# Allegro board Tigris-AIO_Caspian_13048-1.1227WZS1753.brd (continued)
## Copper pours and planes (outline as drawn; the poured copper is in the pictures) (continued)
VCC3 on L3: 1.65,18.14 1.65,247.76 3.3,249.41 101.6,249.41 101.85,249.16 101.85,245.86 101.22,245.22 98.93,245.22 98.68,245.47 92.71,245.47 92.71,243.87 93.22,243.37 93.22,242.86 93.01,242.66 89.18,242.66 84.84,247 51.44,247 50.67,246.24 49.66,246.24 49.15,246.74 30.73,246.74 30.48,246.49 8.13,246.49 5.08,243.44 5.08,190.74 9.46,186.36 9.46,182.04 10.54,180.96 10.54,170.29 14.61,166.23 14.61,137.14 5.71,128.25 5.71,113.52 6.6,112.63 6.6,107.04 5.59,106.03 5.59,94.34 6.86,93.07 6.86,90.28 4.83,88.25 4.83,85.84 6.22,84.44 6.22,61.45 5.71,60.94 5.71,49.77 10.29,45.2 10.29,43.67 9.02,42.4 9.02,41.77 10.54,40.24 10.54,36.43 12.45,34.53 12.45,26.78 22.61,16.62 22.61,14.46 29.84,7.22 35.43,7.22 36.2,6.46 69.98,6.46 71.25,5.19 71.25,2.4 70.61,1.76 18.03,1.76
VCC3 on L4: 110.08,245.22 112.39,242.91 112.39,229.85 112.14,229.6 112.14,226.68 118.11,220.71 119.25,220.71 119.32,220.77 119.38,220.71 123.32,220.71 123.32,220.76 126.59,220.76 126.62,220.74 153.77,220.74 154.56,219.95 154.56,219.44 154.05,218.93 142.24,218.93 141.86,218.55 141.86,217.15 142.24,216.77 143.26,216.77 143.64,217.15 154.76,217.15 159.16,221.55 169.39,221.55 169.82,221.12 170.41,221.12 170.84,221.55 170.84,224.95 169.95,225.84 119.23,225.84 118.96,226.11 118.83,226.11 118.16,226.78 118.16,248.12 117.04,249.23 103.56,249.23 103.5,249.28 99.95,249.28 99.19,248.52 99.19,245.73 99.69,245.22
VCC3 on L4: 144.02,100.19 144.15,100.31 145.29,100.31 145.92,100.95 145.92,106.28 148.59,108.95 149.73,108.95 149.86,108.82 149.86,108.44 147.19,105.77 147.19,100.19 146.05,99.04 144.15,99.04 144.02,99.17
VCC3 on L4: 114.76,57.24 114.43,56.91 114.43,55.1 114.68,54.85 118.87,54.85 122.91,50.81 122.91,45.63 121.95,44.66 121.95,43.52 122.43,43.04 124.61,43.04 124.97,43.39 124.97,51.8 119.53,57.24
VCC3_CAM on BOTTOM: 173.53,221.95 173.23,222.26 173.23,224.27 172.97,224.52 170.05,224.52 169.93,224.39 169.93,222.87 169.8,222.74 167.77,222.74 167.64,222.87 167.64,226.35 169.37,228.08 174.32,228.08 174.6,227.8 174.6,222.23 174.32,221.95 ; 4 cut-outs
VCC3_HDD on TOP: 8.38,89.9 7.87,90.41 7.87,92.57 6.35,94.09 5.46,94.09 5.08,94.47 5.08,96.12 5.46,96.5 7.11,96.5 10.16,93.46 10.16,90.66 9.4,89.9
VCC5_PANEL on TOP: 122.4,217.31 122.17,217.53 122.17,221.98 122.56,222.36 126.36,222.36 126.49,222.23 126.49,219.95 126.62,219.82 126.62,217.66 126.49,217.53 125.86,217.53 125.86,217.56 125.6,217.81 123.55,217.81 123.04,217.31 ; 9 cut-outs
VCC5_PANEL on BOTTOM: 121.54,216.9 121.28,217.15 121.28,223.5 121.41,223.63 124.97,223.63 126.24,222.36 126.24,220.2 122.94,216.9
VCC5_USB on TOP: 106.43,26.02 105.99,26.45 105.99,32.7 106.76,33.46 109.98,33.46 109.98,33.51 110.11,33.51 110.36,33.77 110.36,34.96 110.21,35.11 109.4,35.11 109.09,35.42 109.09,36.13 109.45,36.48 111.12,36.48 111.38,36.23 111.38,34.65 111.63,34.4 112.9,34.4 113.67,33.64 115.32,33.64 115.44,33.51 115.44,32.75 114.91,32.22 114.94,32.19 114.94,27.29 113.67,26.02 ; 9 cut-outs
VCC5_USB on BOTTOM: 181.99,106.28 180.85,107.43 180.85,110.73 181.25,111.13 186.39,111.13 186.74,110.78 186.74,109.05 185.62,107.93 185.62,106.87 185.04,106.28 ; 2 cut-outs
VCC5_USB on BOTTOM: 140.34,31.05 138.89,32.5 136.14,32.5 133.35,35.29 120.14,35.29 119.51,35.92 114.17,35.92 113.67,35.42 113.67,33.38 113.03,32.75 110.87,32.75 110.24,33.38 110.24,35.42 113.28,38.46 121.03,38.46 121.67,37.83 134.49,37.83 136.78,35.54 148.59,35.54 150.88,37.83 150.88,42.02 160.78,51.93 164.72,51.93 165.48,51.16 165.48,49.77 158.18,42.47 158.18,39.49 156.21,37.53 156.21,36.59 155.98,36.59 155.7,36.31 155.7,35.32 153.03,32.65 153.03,32.62 152.27,31.86 150.22,31.86 149.4,31.05
VCC5_USB on BOTTOM: 15.62,22.59 14.73,23.48 14.73,27.92 15.11,28.3 16.26,28.3 16.38,28.18 16.38,24.24 17.4,23.22 17.4,22.84 17.14,22.59 ; 2 cut-outs
VCC5_USB on L4: 167.07,47.93 172.85,53.7 172.85,55.23 174.05,56.44 174.05,58.34 174.88,59.17 174.88,66.4 175.39,66.91 175.39,69.83 175.01,70.21 175.01,78.22 173.99,79.23 173.99,81.39 173.23,82.15 172.34,82.15 169.04,85.45 169.04,92.31 170.43,93.71 178.18,93.71 178.56,94.09 181.61,94.09 183.51,96 183.51,107.68 183.01,108.19 180.09,108.19 180.09,98.92 178.44,97.27 168.91,97.27 165.86,94.22 165.86,82.91 168.66,80.12 168.66,77.83 168.72,77.77 168.72,74.6 168.78,74.53 168.78,73.26 170.18,71.87 170.18,70.21 170.31,70.09 170.31,66.15 168.53,64.37 168.53,59.12 166.62,57.21 166.62,55.99 166.67,55.94 166.67,55.43 163.19,51.95 163.19,49.39 164.66,47.93
VCC12 on TOP: 21.36,72.5 20.83,73.03 20.83,76.31 21.21,76.69 25.18,76.69 25.4,76.48 25.4,75.22 25.43,75.19 25.43,74 25.78,73.64 26.24,73.64 26.24,72.68 26.06,72.5 ; 1 cut-out
VCC12 on BOTTOM: 18.67,182.36 18.29,182.74 18.29,185.28 18.41,185.4 19.3,185.4 19.56,185.15 19.56,182.74 19.18,182.36 ; 1 cut-out
VCC12 on BOTTOM: 12.19,117.2 11.94,117.46 11.94,118.47 12.19,118.73 14.1,118.73 14.35,118.47 14.35,117.59 13.97,117.2 ; 1 cut-out
VCC12_FAN on BOTTOM: 7.75,184.51 6.86,185.4 6.86,190.23 7.62,190.99 14,190.99 14.4,190.59 14.4,189.98 13.46,189.04 13.46,184.64 13.34,184.51 ; 4 cut-outs
VCC12_HDD on TOP: 4.88,103.62 4.65,103.84 4.65,106.31 4.8,106.46 11.53,106.46 11.73,106.26 12.83,106.26 13.31,105.77 17.04,105.77 17.22,105.6 17.22,104 16.84,103.62 ; 2 cut-outs
VCC12_HDD_C on TOP: 17.6,105.65 17.17,106.08 13.46,106.08 13.16,106.38 13.16,107.65 13.31,107.81 18.34,107.81 18.92,107.22 18.92,105.9 18.67,105.65
VCC12_HDD_C on BOTTOM: 18.24,104.84 18.01,105.06 18.01,107.3 18.03,107.32 18.03,111.49 17.4,112.12 13.34,112.12 12.36,113.1 12.36,115.01 13.11,115.76 13.16,115.76 13.46,116.06 13.46,116.82 13.59,116.95 15.49,116.95 16,117.46 17.53,117.46 18.03,116.95 18.41,116.95 20.29,115.07 20.29,105.27 19.86,104.84 ; 2 cut-outs
VCC12CPU on TOP: 13.41,158.66 8.13,163.94 6.6,163.94 1.65,168.89 1.65,188.58 1.83,188.76 1.83,230.87 5.84,234.88 12.45,234.88 14.66,232.67 14.66,224.85 16.13,223.38 19.18,223.38 21.74,220.81 24.99,220.81 25.55,220.25 25.96,220.25 26.16,220.05 26.16,208.8 26.01,208.64 18.62,208.64 18.31,208.34 18.31,201.84 22.17,197.98 24.64,197.98 26.04,196.58 26.04,172.58 24.89,171.43 20.83,171.43 20.19,170.8 20.19,169.91 19.94,169.66 19.05,169.66 17.53,168.13 17.53,165.46 18.03,164.96 18.03,159.65 17.04,158.66
VCC12CPU on BOTTOM: 13,158.58 8.64,162.95 8.64,164.7 8.13,165.21 2.97,165.21 1.83,166.35 1.83,222.92 2.79,223.88 5.46,223.88 6.48,222.87 6.48,181.09 7.37,180.2 9.65,180.2 10.03,180.58 10.92,180.58 11.94,181.59 13.34,181.59 13.46,181.47 13.46,180.83 13.97,180.32 14.73,180.32 17.4,177.66 17.4,174.1 20.07,174.1 20.45,173.72 20.45,164.3 19.32,163.17 19.32,159 18.9,158.58
VIN12V_SYS on TOP: 69.52,29.14 68.91,29.75 67.21,29.75 66.93,30.03 66.93,32.78 70.1,35.95 70.1,46.21 71.02,47.13 76.58,47.13 77.41,46.3 77.41,40.46 78.36,39.51 78.36,37.07 74.14,32.85 74.14,29.85 73.43,29.14 ; 4 cut-outs
VIN12V_SYS on BOTTOM: 72.87,35.57 72.64,35.8 72.64,42.53 73.08,42.96 76.38,42.96 78.23,41.11 78.23,36.03 77.77,35.57
0D95V_VGA on TOP: 108.33,103.74 107.95,104.12 107.95,108.82 109.09,109.97 113.54,109.97 114.05,110.47 121.92,110.47 122.81,109.58 122.81,106.79 122.38,106.36 119.71,106.36 118.8,105.44 118.8,104.58 118.9,104.48 118.9,104.02 118.77,103.9 118.11,103.9 117.96,103.74 ; 2 cut-outs
0D95V_VGA_S0 on TOP: 104.65,95.36 104.39,95.61 104.39,99.55 107.51,102.66 108.01,102.66 108.33,102.98 114.6,102.98 114.88,102.7 114.88,100.26 109.98,95.36
0D95V_VGA_S0 on TOP: 80.4,91.14 79.92,91.62 79.59,91.62 79.13,91.17 78.4,91.17 77.91,91.66 76.79,91.66 75.52,92.93 75.52,94.61 75.79,94.88 75.79,95.64 75.92,95.76 76.5,95.76 76.83,95.43 76.83,94.63 77.01,94.45 79.59,94.45 79.84,94.71 80.35,94.71 82,93.05 82,92.42 80.72,91.14
0D95V_VGA_S0 on BOTTOM: 78.74,91.04 78.61,91.17 78.61,91.68 78.49,91.8 77.72,91.8 77.34,92.19 77.34,94.34 77.22,94.47 76.45,94.47 76.07,94.85 76.07,95.23 76.71,95.87 77.6,95.87 77.72,95.74 77.72,95.11 77.85,94.98 78.23,94.98 78.36,94.85 78.36,93.46 78.74,93.07 81.71,93.07 81.84,93.2 83.82,93.2 84.2,93.58 84.96,93.58 85.03,93.52 85.41,93.52 87.5,95.61 89.15,95.61 89.6,96.06 89.6,96.44 89.66,96.5 89.66,97.98 92.08,100.39 103.91,100.39 106.05,98.26 106.05,95.87 105.66,95.49 94.49,95.49 94.23,95.23 92.2,95.23 91.44,94.47 91.44,93.96 91.06,93.58 89.41,93.58 88.29,92.47 87.4,92.47 86.11,91.17 81.53,91.17 81.41,91.3 79.63,91.3 79.38,91.04 ; 12 cut-outs
1D05V_PWR on TOP: 150.55,105.72 150.39,105.88 150.39,107.86 153.44,110.91 154.05,110.91 154.64,111.49 158.75,111.49 159.51,112.25 160.66,112.25 160.68,112.28 164.82,112.28 164.97,112.12 164.97,106.66 164.72,106.41 161.04,106.41 160.4,105.77 160.02,105.77 159.98,105.74 158.28,105.74 158.27,105.72 ; 2 cut-outs
1D05V_SW on TOP: 168.45,103.64 165.86,106.23 165.86,112.61 168.25,115 172.36,115 172.39,115.02 172.54,114.87 172.54,110.04 172.24,109.74 172.24,107.63 172.54,107.32 172.54,103.9 172.29,103.64
1D05V_SW on L3: 171.7,113.65 167.26,113.65 165.86,112.25 165.86,106.66 166.75,105.77 171.45,105.77 172.21,106.54 172.21,113.14
1D5V_VGA_S0 on TOP: 48.03,84.2 47.9,84.33 45.77,84.33 45.69,84.4 45.69,84.91 45.79,85.01 47.5,85.01 47.62,85.14 47.62,86.03 47.44,86.22 45.97,86.22 45.85,86.34 45.85,96 45.94,96.09 47.37,96.09 47.52,95.94 47.52,93.74 48.09,93.16 48.09,91.35 47.93,91.18 47.92,91.18 47.51,90.78 47.51,89.78 47.12,89.39 47.12,87.61 47.38,87.35 47.95,87.35 48.13,87.53 48.13,88.87 48.26,89 49.02,89 49.86,88.16 49.86,84.61 49.45,84.2 ; 8 cut-outs
1D5V_VGA_S0 on TOP: 46.05,102.11 45.74,102.41 45.74,106.96 45.87,107.09 49.93,107.09 50.59,106.43 50.59,103.3 49.91,102.62 48.03,102.62 47.52,102.11 ; 8 cut-outs
1D5V_VGA_S0 on TOP: 45.72,74.22 45.54,74.4 45.54,75.56 45.74,75.77 45.74,78.79 45.84,78.89 46.48,78.89 46.91,79.32 48.26,79.32 48.79,78.79 48.79,77.95 50.24,76.5 50.24,75.46 49.73,74.95 49.02,74.95 48.28,74.22 ; 5 cut-outs
1D5V_VGA_S0 on TOP: 58.42,59.93 57.66,60.69 57.66,65.77 58.8,66.91 66.8,66.91 67.31,66.4 67.31,61.96 66.67,61.32 63.88,61.32 62.48,59.93
1D5V_VGA_S0 on BOTTOM: 46.58,72.41 45.74,73.25 45.74,78.76 45.92,78.94 47.37,78.94 47.52,79.09 49.32,79.09 49.81,78.61 49.81,77.49 49.32,77.01 48.79,77.01 48.61,76.83 48.61,76.15 49.02,75.74 49.63,75.74 50.01,76.12 50.44,76.12 50.59,75.97 50.59,74.32 50.44,74.17 50.24,74.17 49.73,74.68 49.07,74.68 48.79,74.4 48.79,73.79 49.02,73.56 49.27,73.56 49.45,73.74 49.81,73.74 49.88,73.66 49.88,72.54 49.76,72.41 ; 7 cut-outs
1D5V_VGA_S0 on BOTTOM: 45.85,99.93 45.72,100.06 45.72,106.28 45.99,106.55 47.57,106.55 47.7,106.43 47.7,100.64 47.62,100.57 46.99,100.57 46.35,99.93 ; 9 cut-outs
1D5V_VGA_S0 on BOTTOM: 57.66,77.2 57.66,79.23 58.93,80.5 58.93,84.82 59.05,84.95 59.44,84.95 59.69,85.2 59.69,87.23 58.67,88.25 58.67,91.42 55.88,94.22 55.88,96.12 56.01,96.25 56.39,96.25 58.55,94.09 58.55,93.96 60.07,92.44 60.71,92.44 61.34,91.8 61.34,91.04 62.23,90.15 63.63,90.15 64.64,89.14 69.09,89.14 69.34,89.39 69.34,91.7 69.75,92.11 73.2,92.11 73.66,92.57 73.66,93.84 73.79,93.96 75.06,93.96 75.31,94.22 76.07,94.22 76.2,94.09 76.2,91.93 75.82,91.55 75.82,85.33 75.95,85.2 75.95,81.64 75.56,81.26 74.93,81.26 74.17,80.5 70.1,80.5 68.71,81.9 62.1,81.9 58.67,78.47 58.67,77.71 58.17,77.2 ; 16 cut-outs
1D5V_VGA_S0 on BOTTOM: 49.15,82.9 47.72,84.33 45.92,84.33 45.74,84.51 45.74,87.17 45.92,87.35 47.65,87.35 47.83,87.53 47.83,88.06 46,89.89 46,93.8 46.2,94 47.95,94 48.33,93.62 48.33,89.59 49.76,88.16 49.76,83.11 49.55,82.9 ; 2 cut-outs
1D5V_VGA_S0 on L3: 49.4,79.22 47.24,79.22 46.99,78.97 46.99,74.14 49.4,71.73 54.85,71.73 55.5,72.37 55.5,73.63 54.86,74.27 54.23,74.27 52.7,72.74 50.54,72.74 50.04,73.25 50.04,75.67 49.53,76.17 49.53,79.09
1D5V_VGA_S0 on L4: 61.09,64.24 60.7,64.63 60.45,64.63 60.45,64.62 50.3,64.62 48.51,66.4 48.51,67.8 44.75,71.56 44.75,104.16 51.38,110.79 60.9,110.79 68.96,102.73 71.5,102.73 73.28,100.95 73.28,100.31 76.58,97.01 76.58,94.34 75.82,93.58 75.82,90.66 76.83,89.65 76.83,86.72 78.11,85.45 78.11,85.07 80.01,83.17 81.66,83.17 83.31,81.52 83.31,72.25 82.8,71.74 82.68,71.74 82.42,71.48 82.42,71.43 79.89,68.89 71.18,68.89 66.52,64.24 ; 1 cut-out
1D8V_VGA on TOP: 96.82,61.45 96.06,62.21 96.06,66.86 96.29,67.09 99.29,67.09 99.52,67.32 100.84,67.32 100.86,67.29 100.86,65.64 101.88,64.63 103.89,64.63 104.09,64.42 104.09,61.76 103.78,61.45 ; 2 cut-outs
1D8V_VGA_S0 on TOP: 90.82,97.71 90.71,97.82 90.71,98.23 90.77,98.28 91.19,98.28 92.91,100.01 92.91,100.02 93.19,100.3 93.21,100.3 94.11,101.2 94.11,103.87 94.74,104.5 95,104.5 95.12,104.38 95.12,100.06 95,99.93 94.23,99.93 93.98,99.68 93.88,99.68 91.91,97.71 ; 3 cut-outs
1P5_PCH_PWR on TOP: 124.71,48.75 123.95,49.51 123.95,55.1 124.33,55.48 126.75,55.48 127.89,54.34 127.89,52.18 129.03,51.04 131.19,51.04 131.32,50.91 131.32,48.88 131.19,48.75 ; 6 cut-outs
1P5_PCH_PWR on BOTTOM: 124.33,48.37 124.08,48.62 124.08,53.58 124.33,53.83 128.65,53.83 129.03,53.45 129.03,48.75 128.65,48.37
1P5_PCH_VCC3 on TOP: 131.95,44.05 131.7,44.31 131.7,52.69 131.95,52.94 134.24,52.94 134.62,52.56 134.62,49.77 134.75,49.64 136.4,49.64 136.53,49.51 136.53,47.23 133.35,44.05
3D3V_PWR on TOP: 98.7,45.75 98.48,45.98 90.93,45.98 90.37,46.54 90.37,51.09 92.15,52.87 95.28,52.87 96.88,51.27 98.96,51.27 99.39,50.83 99.39,46.26 98.88,45.75
3D3V_PWR on BOTTOM: 97.84,44.97 97.83,44.97 97.81,44.97 97.71,45.07 97.71,45.12 91.77,45.12 91.19,45.7 91.19,52.87 91.67,53.35 98.22,53.35 98.53,53.04 98.53,45.88 98.63,45.78 98.63,45.09 98.5,44.97 ; 1 cut-out
3D3V_VGA_S0 on TOP: 84.68,69.72 83.84,70.56 83.57,70.56 83.57,71.74 83.82,71.99 87.63,71.99 87.88,71.74 87.88,70.21 87.87,70.21 87.63,69.98 85.57,69.98 85.32,69.72 ; 1 cut-out
3D3V_VGA_S0 on BOTTOM: 50.77,133.21 49.91,134.07 49.91,142.78 46.23,146.47 46.23,148.8 46.61,149.18 50.44,149.18 53.72,145.91 53.72,133.77 53.16,133.21 ; 7 cut-outs
3D3V_VGA_S0 on L4: 51.16,131.71 54.08,131.71 54.69,132.32 54.69,140.19 52.3,142.58 51.05,142.58 50.74,142.26 50.71,142.26 50.55,142.1 50.55,131.94 50.8,131.68 51.13,131.68
1589_LX on TOP: 32.38,80.91 32.38,82.51 31.62,83.27 29.16,83.27 28.91,83.52 28.91,95.51 29.26,95.87 35.05,95.87 35.69,95.23 35.69,90.41 34.67,89.39 32.64,89.39 31.85,88.6 31.85,85.38 33.05,84.18 33.05,80.91
62883AGND on BOTTOM: 35.69,130.79 35.36,131.12 35.36,133.16 38.51,136.31 38.79,136.31 39.14,136.66 39.14,141.49 39.37,141.72 39.37,146.01 39.88,146.52 43.21,146.52 43.92,145.81 43.92,133.28 42.32,131.68 37.59,131.68 36.7,130.79 ; 6 cut-outs
CAP_1 on TOP: 59.69,35.8 59.56,35.92 59.56,36.94 59.82,37.19 60.33,37.19 60.58,36.94 60.58,36.05 60.33,35.8
CR_1P2V_LDOIN on BOTTOM: 178.69,153.53 178.56,153.65 178.56,154.16 178.94,154.54 179.32,154.54 179.71,154.92 179.71,155.18 180.09,155.56 180.59,155.56 180.59,154.8 179.32,153.53
CR_1P2V_LDOOUT on BOTTOM: 178.69,158.86 177.67,159.88 177.67,163.43 177.8,163.56 178.94,163.56 179.07,163.43 179.07,162.67 178.94,162.54 178.94,160.38 179.07,160.26 179.83,160.26 180.21,159.88 180.21,158.99 180.09,158.86 ; 5 cut-outs
CR_3P3V_PECI on BOTTOM: 178.69,154.67 178.56,154.8 178.56,155.43 178.94,155.81 179.83,155.81 179.83,155.56 179.45,155.18 179.45,154.92 179.2,154.67
DCBATOUT_1589 on TOP: 35.28,79.69 34.92,80.04 34.92,82.94 32.38,85.48 32.38,88.27 33.07,88.96 36.73,88.96 36.83,88.86 36.83,87.89 37.41,87.31 37.41,79.69 ; 1 cut-out
DCIN_+12V on TOP: 9.96,132.62 8.36,134.22 8.36,139.33 9.12,140.09 13.59,140.09 15.39,138.29 18.97,138.29 19.2,138.06 19.2,136.15 19.05,136 14.86,136 11.48,132.62
DCIN_+12V on BOTTOM: 17.96,129.98 17.81,130.13 17.81,130.67 17.27,131.2 9.55,131.2 7.87,132.88 7.87,139.18 7.24,139.81 7.24,142.48 8.64,143.87 13.08,143.87 14.1,142.86 17.48,142.86 17.7,143.09 17.7,145.93 17.55,146.08 17.55,146.87 17.73,147.05 19.25,147.05 19.46,146.85 19.46,146.31 19.05,145.91 19.05,144.99 18.77,144.71 18.77,130.21 18.54,129.98 ; 14 cut-outs
DDR_SW on TOP: 174.02,198.56 168.1,204.48 168.1,214.79 168.35,215.05 171.63,215.05 171.81,214.87 171.81,213.19 172.16,212.84 179.15,212.84 179.55,212.43 179.55,207.12 179.22,206.79 177.83,206.79 177.44,206.41 177.44,204.73 177.83,204.35 179.22,204.35 179.55,204.02 179.55,198.87 179.25,198.56
DDR_SW on BOTTOM: 173.86,198.74 168.15,204.45 168.15,211.95 169.04,212.84 178.69,212.84 179.58,211.95 179.58,199.25 179.07,198.74
DDR_VREF_PWR on BOTTOM: 133.48,108.19 132.84,108.82 132.84,110.85 132.97,110.98 137.29,110.98 138.18,111.87 138.18,114.41 139.06,115.3 145.54,115.3 146.05,114.79 146.05,109.08 145.16,108.19 ; 1 cut-out
DPLVDS_PIN12 on TOP: 127.81,206.92 127.64,207.1 127.64,208.52 128.02,208.9 128.52,208.9 128.65,208.77 128.65,208.14 128.78,208.01 129.03,208.01 129.18,207.86 129.18,207.02 129.08,206.92
DPLVDS_PIN12 on BOTTOM: 128.78,207.12 128.52,207.37 128.52,207.76 128.78,208.01 129.54,208.01 129.67,207.88 129.67,207.25 129.54,207.12
HDD_LED_5V on TOP: 2.92,40.12 2.67,40.37 2.67,45.96 3.81,47.1 6.48,47.1 6.73,46.85 6.73,44.56 8.89,42.4 8.89,40.37 8.64,40.12
LAN_1P05_OUT on TOP: 26.54,37.96 26.04,38.46 26.04,39.25 25.91,39.38 25.91,43.54 26.16,43.8 29.46,43.8 29.72,43.54 29.72,42.78 29.84,42.66 30.86,42.66 30.99,42.53 30.99,41.77 30.86,41.64 28.83,41.64 27.15,39.96 27.15,39.38 27.43,39.1 27.43,37.96 ; 2 cut-outs
MPV18 on BOTTOM: 75.9,75.24 75.77,75.37 75.77,80.17 75.56,80.37 75.16,80.37 75.06,80.48 75.06,81.04 75.16,81.14 75.69,81.14 76.12,80.71 76.12,80.22 76.33,80.02 76.33,78.98 76.45,78.85 76.45,75.35 76.35,75.24
Net_1 on BOTTOM: 4.95,130.29 9.02,130.29 9.14,130.16 9.14,128 8.79,127.64 4.8,127.64 4.57,127.87 4.57,129.9
PWM1_LX on TOP: 26.92,208.77 26.67,209.03 26.67,212.33 26.8,212.45 28.57,212.45 28.7,212.58 28.7,214.99 28.57,215.12 26.8,215.12 26.67,215.25 26.67,218.68 26.8,218.8 28.7,218.8 28.83,218.93 28.83,221.09 28.32,221.6 26.06,221.6 25.68,221.98 25.68,226.3 26.06,226.68 31.27,226.68 31.52,226.42 31.52,224.65 31.78,224.39 34.06,224.39 34.32,224.65 34.32,226.3 34.7,226.68 39.58,226.68 39.96,226.3 39.96,219.55 39.55,219.14 37.92,219.14 37.39,218.6 37.39,217.74 34.16,214.51 34.16,209.03 33.91,208.77
PWM1_LX on BOTTOM: 29.21,208.77 28.83,209.15 28.83,221.09 28.32,221.6 26.04,221.6 25.68,221.95 25.68,226.3 26.06,226.68 31.27,226.68 31.52,226.42 31.52,224.65 31.78,224.39 34.06,224.39 34.32,224.65 34.32,226.3 34.7,226.68 39.58,226.68 39.96,226.3 39.96,219.55 39.55,219.14 35,219.14 34.67,218.8 34.67,216.9 35.23,216.34 35.23,215.58 34.16,214.51 34.16,209.03 33.91,208.77
PWM1_LX on L3: 29.41,222.67 39.67,222.67 39.95,222.39 39.95,219.54 39.55,219.14 37.92,219.14 37.39,218.6 37.39,217.74 34.16,214.51 34.16,209.03 33.91,208.77 29.21,208.77 28.83,209.15 28.83,222.08
PWM2_LX on TOP: 26.67,185.78 26.54,185.91 26.54,189.09 26.67,189.21 28.19,189.21 28.57,189.59 28.57,191.88 28.32,192.13 26.67,192.13 26.54,192.26 26.54,195.31 26.67,195.44 28.64,195.44 28.77,195.56 28.77,197.66 28.77,197.66 28.77,198.29 28.45,198.61 26.44,198.61 26.06,198.99 26.06,203.31 26.44,203.69 31.65,203.69 31.9,203.44 31.9,201.66 32.16,201.41 34.44,201.41 34.7,201.66 34.7,203.31 35.08,203.69 39.96,203.69 40.34,203.31 40.34,195.9 40.11,195.67 37.21,195.67 36.83,195.28 36.83,193.89 34.29,191.35 34.29,186.17 33.91,185.78
PWM2_LX on BOTTOM: 29.01,185.78 28.75,186.04 28.75,198.31 28.45,198.61 26.42,198.61 26.06,198.97 26.06,203.31 26.44,203.69 31.65,203.69 31.9,203.44 31.9,201.66 32.16,201.41 34.44,201.41 34.7,201.66 34.7,203.31 35.08,203.69 39.96,203.69 40.34,203.31 40.34,196.26 39.75,195.67 35.31,195.67 35.08,195.44 35.05,195.44 34.8,195.18 34.8,194.01 35.48,193.33 35.48,192.54 34.29,191.35 34.29,186.17 33.91,185.78
PWM2_LX on L3: 29.39,199.6 39.88,199.6 40.34,199.15 40.34,195.89 40.11,195.67 37.21,195.67 36.83,195.28 36.83,193.89 34.29,191.35 34.29,186.17 33.91,185.78 29.01,185.78 28.75,186.04 28.75,198.97
PWM3_LX on TOP: 26.92,166.29 26.54,166.67 26.54,175.88 26.67,176.01 28.57,176.01 28.7,176.13 28.7,178.55 28.42,178.83 26.67,178.83 26.54,178.95 26.54,182.23 26.67,182.36 30.53,182.36 30.99,181.9 30.99,180.3 31.39,179.89 33.22,179.89 40.83,172.29 40.83,166.67 40.45,166.29 35.24,166.29 34.99,166.54 34.99,168.32 34.73,168.57 32.45,168.57 32.19,168.32 32.19,166.67 31.81,166.29
PWM3_LX on BOTTOM: 26.92,166.29 26.54,166.67 26.54,175.9 26.14,176.31 25.27,176.31 25.02,176.56 25.02,177.07 25.25,177.3 28.57,177.3 28.7,177.43 28.7,182.03 29.03,182.36 30.53,182.36 30.99,181.9 30.99,179.18 33.32,176.84 36.27,176.84 40.83,172.29 40.83,166.67 40.45,166.29 35.24,166.29 34.99,166.54 34.99,168.32 34.73,168.57 32.45,168.57 32.19,168.32 32.19,166.67 31.81,166.29 ; 1 cut-out
PWM3_LX on L3: 28.7,182.03 28.7,171.08 29.49,170.29 40.28,170.29 40.82,170.82 40.82,172.3 33.22,179.89 31.39,179.89 30.99,180.3 30.99,181.9 30.53,182.36 29.03,182.36
PWR_VGA_CORE_PHASE1 on TOP: 25.65,103.36 25.4,103.62 25.4,108.95 24.77,109.58 24.77,113.27 26.47,113.27 26.7,113.5 26.7,115.27 26.04,115.93 24.97,115.93 24.71,116.19 24.71,119.64 24.89,119.82 30.43,119.82 31.43,118.82 31.43,115.11 37.64,108.9 37.64,103.57 37.44,103.36
PWR_VGA_CORE_PHASE1 on BOTTOM: 29.36,103.36 29.01,103.72 29.01,106.31 28.7,106.61 25.98,106.61 25.4,107.2 25.4,113.62 26.7,114.92 26.7,118.12 27.41,118.83 30.89,118.83 31.42,118.3 31.42,114.74 32.13,114.03 32.51,114.03 32.89,114.41 33.17,114.41 37.69,109.89 37.69,103.57 37.49,103.36
RING2 on TOP: 180.31,82 180.21,82.1 180.21,83.02 179.32,83.91 179.32,85.4 179.4,85.48 179.4,86.37 179.63,86.37 179.63,85.4 179.73,85.3 179.73,84.85 180.29,84.29 180.72,84.29 181.03,83.98 181.03,82.15 180.87,82
RING2 on BOTTOM: 180.21,83.3 179.83,83.68 179.83,83.93 180.09,84.18 180.47,84.18 180.97,84.69 182.5,84.69 184.91,87.11 189.36,87.11 189.61,86.85 189.61,86.04 189.53,85.96 185.93,85.96 183.51,83.55 182.25,83.55 181.99,83.3
RT8243_PHASE1 on TOP: 75.82,23.61 75.44,23.99 75.44,32.14 75.84,32.55 81.33,32.55 81.92,31.96 81.92,24.49 81.41,23.99 77.85,23.99 77.47,23.61
RT8243_PHASE1 on BOTTOM: 78.08,24.11 77.32,24.88 77.32,31.28 77.67,31.63 81.53,31.63 81.92,31.25 81.92,24.75 81.28,24.11
RT8243_PHASE1 on L3: 75.95,32.5 81.38,32.5 81.92,31.96 81.92,24.24 81.52,23.85 75.83,23.85 75.44,24.24 75.44,31.99
RT8243_PHASE2 on TOP: 78.82,42.63 78.49,42.96 78.49,45.7 78.74,45.96 80.95,45.96 81.28,46.29 81.28,47.71 81.03,47.96 78.97,47.96 78.87,48.07 78.87,52.38 79.15,52.66 84.76,52.66 85.47,51.95 85.47,43.19 84.91,42.63
RT8243_PHASE2 on BOTTOM: 81.79,49.89 81.41,50.28 81.41,52.64 81.46,52.69 84.84,52.69 84.84,50.28 84.45,49.89
RT8243_PHASE2 on L3: 85.22,51.16 85.47,50.91 85.47,43.09 85.04,42.66 80.21,42.66 79.83,43.04 79.83,50.53 80.47,51.16
SB3V on TOP: 54.86,30.72 54.74,30.84 54.74,32.11 54.86,32.24 57.28,32.24 57.4,32.11 57.4,30.84 57.28,30.72
SB3V on TOP: 86.61,225.28 85.22,226.68 85.22,233.79 85.72,234.3 88.39,234.3 88.52,234.17 88.52,229.09 88.9,228.71 93.47,228.71 93.92,228.27 93.92,225.35 93.85,225.28 ; 4 cut-outs
SB3V on TOP: 30.23,61.2 30.1,61.32 30.1,64.37 30.61,64.88 32.26,64.88 32.58,64.56 32.64,64.63 35.81,64.63 36.2,64.25 36.2,61.32 36.07,61.2 ; 2 cut-outs
SB3V on BOTTOM: 31.37,24.62 31.11,24.88 31.11,30.59 33.4,32.88 34.54,32.88 35.05,33.38 35.94,33.38 37.08,34.53 37.08,36.56 37.72,37.19 39.75,37.19 40.13,36.81 40.13,35.8 39.5,35.16 39.5,33.26 39.12,32.88 39.12,32.11 38.61,31.61 35.69,31.61 33.15,29.07 33.15,25 32.77,24.62 ; 2 cut-outs
SB3V on BOTTOM: 38.38,44.41 38.04,44.75 38.04,45.26 38.02,45.27 38.02,49.08 38.99,50.05 38.99,50.1 40.41,50.1 40.59,49.92 40.59,46.92 40.46,46.8 39.24,46.8 39.04,46.59 39.04,45.55 39.51,45.08 40.12,45.08 40.26,44.94 40.92,44.94 40.92,44.56 40.77,44.41
SB3V on BOTTOM: 165.86,222.82 165.61,223.07 165.61,223.55 164.8,224.37 164.8,226.48 165.13,226.81 167,226.81 167.26,226.55 167.26,222.92 167.16,222.82 ; 1 cut-out
SB3V on BOTTOM: 12.95,62.59 12.45,63.1 12.45,65.64 13.59,66.79 32,66.79 32.89,65.9 34.29,65.9 34.67,65.52 34.67,62.59
SB3V on BOTTOM: 147.52,91.98 147.45,92.06 147.45,92.57 147.57,92.69 147.96,92.69 148.21,92.95 148.21,93.84 148.08,93.96 142.42,93.96 142.3,94.09 142.3,94.48 142.39,94.57 142.96,94.57 143,94.62 143,95.72 143.27,95.98 143.27,96.52 143.36,96.61 144.3,96.61 144.42,96.48 144.42,95.72 145.03,95.11 146.51,95.11 146.96,95.56 146.96,95.97 147.21,96.21 148.04,96.21 148.29,96.45 149.17,96.45 149.38,96.25 149.38,93.41 150.14,92.64 150.14,92.06 150.06,91.98 ; 13 cut-outs
SB3V on L4: 23.39,50.87 22.76,50.24 22.7,50.24 20.32,47.86 20.32,42.53 22.73,40.12 22.73,34.27 25.91,31.1 26.8,31.1 29.08,28.81 29.08,26.53 30.99,24.62 32,24.62 32.08,24.7 32.08,25.13 31.88,25.33 31.88,29.7 26.75,34.83 26.75,38.87 26.49,39.13 26.47,39.13 25.78,39.81 25.78,41.77 23.62,43.93 23.62,47.1 26.44,49.92 26.44,55.69 33.76,63 33.76,64.09 33.78,64.12 33.78,64.14 33.02,64.91 32.03,64.91 32,64.88 30.48,64.88 23.39,57.79
SB3V on L4: 13.84,128.76 13.84,61.83 13.34,61.32 9.7,61.32 9.27,61.76 9.27,84.82 7.87,86.22 7.87,112.38 7.37,112.89 7.37,130.16 14.99,137.78 14.99,138.29 15.62,138.92 15.62,146.67 13.28,149.01 13.28,159.29 13.29,159.3 13.29,161.89 8.38,166.8 8.38,171.81 8.64,172.07 8.64,182.99 6.22,185.4 6.22,241.54 10.03,245.35 66.93,245.35 71.12,241.16 71.12,240.52 77.6,234.04 87.63,234.04 88.27,233.41 88.27,230.87 87.76,230.36 75.95,230.36 66.14,240.17 46.58,240.17 46.41,240.34 46.35,240.34 45.42,241.28 13.59,241.28 10.16,237.85 10.16,193.02 13.08,190.1 13.08,183.12 14.86,181.34 14.86,168 16.76,166.1 16.76,163.18 19.28,160.66 19.28,151.34 22.05,148.57 22.05,138.59 20.4,136.94 20.4,135.32
SB5V on TOP: 22.02,140.95 21.74,141.23 21.74,144.23 21.87,144.36 22.35,144.36 22.56,144.15 22.56,143.54 23.88,142.22 23.88,141.46 23.37,140.95 ; 1 cut-out
SB5V on BOTTOM: 118.11,33.26 117.47,33.89 117.47,35.67 117.6,35.8 118.36,35.8 118.49,35.67 118.49,35.16 118.62,35.04 122.81,35.04 122.81,34.91 123.19,34.53 123.19,33.64 122.81,33.26 ; 1 cut-out
SLEEVE on TOP: 180.26,84.46 179.83,84.9 179.83,86.47 180.01,86.47 180.04,86.45 180.04,85.61 180.37,85.28 180.47,85.28 180.7,85.05 180.7,84.59 180.57,84.46
SLEEVE on BOTTOM: 179.96,84.44 179.58,84.82 179.58,84.95 180.85,86.22 182.63,86.22 183.39,86.98 183.39,88.25 183.9,88.76 186.44,88.76 186.69,88.5 189.18,88.5 189.41,88.27 189.41,87.44 189.33,87.36 184.91,87.36 182.37,84.82 180.59,84.82 180.21,84.44
SPKR_L+_C on TOP: 137.79,27.92 137.79,28.81 142.24,28.81 143.26,29.83 150.62,29.83 150.75,29.7 150.75,28.81 150.5,28.56 144.27,28.56 143.64,27.92
SPKR_L-_C on TOP: 137.79,26.4 137.79,27.29 141.35,27.29 141.6,27.54 143.64,27.54 144.4,28.3 149.99,28.3 150.5,27.8 150.5,27.16 150.11,26.78 144.53,26.78 144.15,26.4
SPKR_R+_C on TOP: 144.02,22.72 142.24,24.49 141.6,24.49 141.22,24.88 137.79,24.88 137.79,25.76 142.75,25.76 144.4,24.11 149.35,24.11 149.73,23.73 149.73,23.22 149.22,22.72
SPKR_R-_C on TOP: 143.51,21.19 141.48,23.22 137.92,23.22 137.67,23.48 137.67,24.24 142.11,24.24 143.89,22.46 149.22,22.46 149.61,22.08 149.61,21.45 149.35,21.19
SWR_LX on BOTTOM: 122.94,208.9 122.68,209.15 122.68,210.17 122.94,210.42 126.75,210.42 127.13,210.04 127.13,209.15 126.87,208.9
TP_VCC12 on TOP: 22.66,62.47 18.54,66.58 18.54,69.2 19.35,70.01 26.04,70.01 26.29,69.76 26.29,62.98 25.78,62.47 ; 1 cut-out
TP_VCC12_C on TOP: 26.85,65.77 26.62,66 26.62,73.26 26.72,73.36 29.44,73.36 29.72,73.09 29.72,66.02 29.46,65.77 ; 5 cut-outs
USBVCC01 on TOP: 180.97,128.2 180.82,128.36 180.82,131.3 181.03,131.51 181.1,131.51 181.28,131.68 191.9,131.68 192.91,130.67 192.91,129.32 192.41,128.81 190.25,128.81 189.64,128.2 ; 2 cut-outs
USBVCC01 on TOP: 191.39,107.78 189.94,109.23 189.94,109.79 188.98,110.75 181.91,110.75 180.54,112.12 180.54,113.67 180.92,114.06 188.37,114.06 192.89,109.53 192.89,108.26 192.41,107.78 ; 2 cut-outs
USBVCC01 on BOTTOM: 181.28,111.85 180.8,112.33 180.8,113.73 181.43,114.36 182.3,114.36 182.5,114.56 182.5,115.3 182.55,115.35 183.29,115.35 183.34,115.3 183.34,114.56 183.54,114.36 186.41,114.36 186.74,114.03 186.74,112.18 186.41,111.85
USBVCC01 on L4: 180.31,112.58 180.31,114.39 181.89,115.96 181.89,118.47 182.37,118.96 182.37,121.01 181.36,122.03 181.36,128.51 181.86,129.02 186.06,129.02 186.56,128.51 186.56,118.35 186.25,118.03 186.25,114.73 183.69,112.18 180.72,112.18
USBVCC89 on TOP: 86.06,8.62 85.98,8.7 85.98,10.27 86.49,10.78 93.09,10.78 93.47,10.4 93.47,9.13 92.96,8.62 ; 2 cut-outs
USBVCC89 on TOP: 116.97,25.13 115.32,26.78 115.32,32.11 115.7,32.5 117.47,32.5 117.6,32.62 117.6,33.51 117.98,33.89 118.62,33.89 119.25,33.26 119.25,29.83 119.21,29.79 119.21,25.6 118.75,25.13 ; 2 cut-outs
USBVCC89 on BOTTOM: 89.15,8.62 88.52,9.25 88.52,13.7 90.17,15.35 100.25,15.35 100.84,15.94 100.84,16.87 111.51,27.54 118.11,27.54 119.76,25.89 119.76,22.08 113.67,15.99 111.76,15.99 111.12,15.35 111.12,9.76 109.98,8.62
USBVCC1011 on TOP: 109.98,10.27 109.73,10.52 109.73,20.94 108.84,21.83 106.68,21.83 106.17,22.34 106.17,24.88 106.68,25.38 116.33,25.38 117.35,24.37 117.35,18.27 116.46,17.38 116.46,11.67 115.06,10.27 ; 2 cut-outs
USBVCC1011 on BOTTOM: 112.9,9 111.38,10.52 111.38,15.22 111.63,15.48 114.05,15.48 116.84,18.27 128.4,18.27 130.18,16.49 132.66,16.49 134.49,14.67 134.49,10.32 133.17,9
USBVCCTP on TOP: 6.07,24.32 5.82,24.57 5.82,25.51 6.2,25.89 9.09,25.89 9.4,25.59 9.4,24.57 9.14,24.32
USBVCCTP on BOTTOM: 12.57,23.73 11.94,24.37 9.22,24.37 9.19,24.34 8.99,24.34 8.74,24.6 8.74,26.17 9.6,27.03 11.05,27.03 11.94,27.92 11.94,28.56 12.32,28.94 14.1,28.94 14.22,28.81 14.22,24.11 13.84,23.73 ; 2 cut-outs
V_1P05_LAN on TOP: 30.1,42.91 29.97,43.04 29.97,43.67 29.59,44.05 25.4,44.05 25.27,44.18 25.27,45.07 25.4,45.2 25.91,45.2 26.04,45.32 26.04,45.7 26.54,46.21 31.11,46.21 31.24,46.08 31.24,45.2 30.99,44.94 30.99,43.04 30.86,42.91 ; 2 cut-outs
V_1P05_LAN on BOTTOM: 27.69,32.88 25.15,35.42 25.15,37.07 27.9,39.82 30.65,39.82 31.88,38.59 31.88,33.89 30.86,32.88 ; 21 cut-outs
V_1P5_PCH on TOP: 121.79,55.99 121.41,56.37 121.41,58.53 118.75,61.2 115.95,61.2 114.3,62.85 114.3,69.07 116.2,70.98 116.2,83.42 119,86.22 124.97,86.22 125.22,85.96 125.22,85.84 125.86,85.2 126.24,85.2 126.24,83.42 125.98,83.17 124.71,83.17 124.59,83.3 121.67,83.3 121.54,83.17 121.54,82.41 121.79,82.15 125.35,82.15 125.86,81.64 125.86,81.01 125.35,80.5 120.02,80.5 118.11,78.6 118.11,76.06 119.25,74.91 119.89,74.91 120.4,74.41 120.4,73.9 120.14,73.64 119.25,73.64 119,73.39 119,72.12 120.27,70.85 124.08,70.85 124.46,71.23 124.97,71.23 125.09,71.1 125.98,71.1 126.11,70.98 126.11,70.34 125.86,70.09 123.44,70.09 123.06,69.71 123.06,69.58 122.43,68.94 117.22,68.94 116.4,68.12 116.4,65.13 117.67,63.86 122.05,63.86 123.32,65.13 123.83,65.13 125.35,66.66 126.29,66.66 126.31,66.63 126.31,66.1 125.98,65.77 125.09,65.77 124.71,65.39 124.71,59.17 126.11,59.17 126.24,59.29 126.24,64.88 126.49,65.13 127.13,65.13 127.89,64.37 130.56,64.37 130.43,64.25 130.43,62.34 128.91,60.82 129.03,60.69 129.03,58.02 127,55.99 ; 8 cut-outs
V_1P05_PCH on TOP: 150.83,102.6 150.5,102.93 150.5,104.94 150.62,105.06 158.01,105.06 158.22,104.86 158.22,103.44 157.38,102.6
V_1P05_PCH on BOTTOM: 151,100.95 148.92,103.03 148.39,103.03 148.06,102.7 148.06,102.12 147.83,101.89 143.65,101.89 143.37,102.17 143.37,105.25 143.61,105.5 153.95,105.5 154.56,104.89 154.56,101.91 153.59,100.95 ; 5 cut-outs
V_1P5_PCH on BOTTOM: 130.83,68.31 130.74,68.41 130.74,68.87 130.93,69.07 132.06,69.07 132.17,68.95 132.17,68.48 132.01,68.32 130.84,68.32
V_1P05_PCH on L3: 146.18,85.9 146.18,75.29 145.29,74.41 140.72,74.41 140.08,73.77 140.08,72.25 139.45,71.61 139.45,70.6 139.19,70.34 132.89,70.34 132.89,70.49 132.99,70.6 132.99,71.26 131.98,72.27 131.93,72.27 131.88,72.22 131.88,72.15 132.69,71.33 132.69,70.72 132.51,70.55 132.51,70.34 132.08,70.34 130.05,72.37 130.05,89.9 131.52,91.37 131.52,91.45 131.5,91.47 131.5,94.01 136.02,98.54 136.02,100.06 136.78,100.82 138.3,100.82 141.22,103.74 154.38,103.74 154.64,103.49 154.64,100.52 147.7,93.58 146.56,93.58 146.24,93.27 146.24,85.96 ; 2 cut-outs
V_3_CARD on TOP: 181.74,151.88 181.61,152 181.61,152.89 183.13,154.42 186.66,154.42 186.87,154.21 186.87,153.2 185.99,152.32 183.81,152.32 183.36,151.88 ; 2 cut-outs
V_3P3_A on TOP: 33.02,57.26 32.21,58.07 32.21,59.93 32.51,60.23 33.53,60.23 33.78,59.98 33.78,59.04 34.42,58.4 36.17,58.4 36.45,58.68 36.45,64.37 36.96,64.88 38.23,64.88 41.78,68.44 43.43,68.44 43.81,68.06 43.81,64.88 40.64,61.71 40.64,58.48 39.42,57.26
V_3P3_A on TOP: 122.68,29.09 122.43,29.35 122.43,34.27 122.81,34.65 126.24,34.65 126.49,34.4 126.49,29.45 126.14,29.09
V_3P3_A on BOTTOM: 99.31,46.21 99.06,46.47 99.06,52.82 99.44,53.2 102.49,53.2 102.74,53.45 102.74,55.74 102.36,56.12 95.12,56.12 92.71,53.7 74.17,53.7 72.26,51.8 70.74,51.8 70.36,52.18 70.36,55.86 65.98,60.25 65.98,64.31 64.77,65.52 59.18,65.52 58.55,64.88 58.55,64.75 56.77,64.75 56.71,64.69 53.4,64.69 53.09,64.37 42.42,64.37 41.66,65.13 41.66,67.8 42.42,68.56 67.44,68.56 69.6,66.4 69.6,62.09 74.17,57.51 89.92,57.51 93.47,61.07 96.14,61.07 96.27,60.94 97.66,60.94 98.17,61.45 106.55,61.45 107.7,60.31 107.7,47.48 106.43,46.21
V_3P3_A on L3: 105.92,51.29 100.33,51.29 99.57,50.53 99.57,43.54 107.67,35.44 112.17,35.44 117.14,30.46 126.64,30.46 126.94,30.76 126.94,33.7 125.76,34.88 120.52,34.88 113.13,42.27 108.97,42.27 106.93,44.31 106.93,50.28
V_3P3_EPW on TOP: 145.29,103.62 143.38,105.52 140.46,105.52 140.34,105.65 140.34,107.32 142.77,109.76 142.77,110.19 142.9,110.32 144.93,110.32 145.3,109.95 145.3,108.53 145.54,108.29 146.71,108.29 146.94,108.06 146.94,103.62 ; 1 cut-out
V_3P3_LAN on BOTTOM: 25.02,26.27 24.66,26.63 23.93,26.63 23.55,27.01 23.55,27.64 23.95,28.05 26.04,28.05 26.24,28.25 26.24,28.89 26.71,29.36 26.71,29.89 26.04,30.57 26.04,30.74 26.05,30.76 26.05,31.21 25.02,32.24 25.02,33.38 25.53,33.89 26.42,33.89 27.69,32.62 30.99,32.62 32,33.64 32,37.58 32.51,38.08 36.83,38.08 37.08,37.83 37.08,35.42 36.58,34.91 35.56,34.91 35.18,34.53 33.4,34.53 33.15,34.27 33.15,33.51 31.37,31.73 29.59,31.73 29.21,31.35 29.21,28.94 29.59,28.56 30.61,28.56 30.99,28.18 30.99,27.8 29.46,26.27 ; 12 cut-outs
V_3P3_LAN_VDDSREG on TOP: 28.7,40.62 28.57,40.75 28.57,41.26 28.83,41.51 30.99,41.51 31.11,41.64 31.11,42.4 31.37,42.66 33.27,42.66 33.4,42.53 33.4,41.13 32.89,40.62
V_3P3_LAN_VDDSREG on BOTTOM: 35.56,38.34 33.66,40.24 28.32,40.24 28.19,40.37 28.19,41 28.57,41.39 36.2,41.39 36.45,41.13 36.45,38.46 36.32,38.34
V_3P3_PCIVAUX on TOP: 94.74,225.41 94.61,225.54 94.61,229.47 95,229.85 97.28,229.85 97.79,229.35 97.92,229.35 98.17,229.6 98.17,244.71 97.66,245.22 97.66,248.4 98.55,249.28 111.12,249.28 111.25,249.16 111.25,247.25 111.09,247.09 109.08,247.09 108.86,246.87 108.86,245.86 107.95,245.86 107.19,246.62 105.03,246.62 104.52,247.13 100.33,247.13 99.69,246.49 99.69,245.86 100.08,245.47 100.08,228.46 100.2,228.33 100.2,226.68 98.93,225.41 ; 6 cut-outs
V_3P3_PCIVAUX on TOP: 107.06,226.68 106.93,226.81 106.93,228.08 108.08,229.22 108.84,229.22 108.84,228.33 109.09,228.08 110.49,228.08 110.62,227.95 110.62,227.82 109.47,226.68
V_3P3_PCIVAUX on BOTTOM: 96.14,226.42 95.89,226.68 95.89,227.44 96.58,228.14 96.58,228.39 97.54,229.35 103.63,229.35 104.27,228.71 108.71,228.71 108.84,228.58 108.84,227.19 108.33,226.68 104.78,226.68 104.52,226.42 ; 4 cut-outs
V_5_LCD1 on BOTTOM: 118.36,215.5 117.98,215.88 117.98,216.14 117.73,216.39 116.46,216.39 116.2,216.65 116.2,217.28 116.33,217.41 117.35,217.41 117.47,217.53 118.87,217.53 119.13,217.28 119.13,215.76 118.87,215.5
V_5_LCD2 on BOTTOM: 119.41,216.9 119.25,217.05 119.25,217.43 118.92,217.76 118.01,217.76 117.86,217.92 117.86,221.09 117.58,221.37 115.24,221.37 115.06,221.55 115.06,223.28 115.42,223.63 118.11,223.63 118.36,223.88 118.36,224.52 118.62,224.77 119.38,224.77 119.89,224.27 119.89,223.76 120.02,223.63 120.02,220.94 120.78,220.18 120.78,217.13 120.55,216.9 ; 3 cut-outs
V_5HDD on TOP: 11.89,76.79 10.03,78.65 10.03,87.02 12.03,89.01 12.03,90.5 12.32,90.79 12.32,93.2 12.29,93.2 11.56,93.94 10.19,93.94 7.59,96.53 7.59,98.26 7.32,98.54 4.95,98.54 4.67,98.82 4.67,101.2 5,101.53 12.12,101.53 14.68,98.97 14.68,94.04 16.79,91.93 16.79,89.11 17.4,88.5 20.75,88.5 21.15,88.11 21.15,85.34 20.62,84.82 17.48,84.82 15.24,87.06 13.28,87.06 13.06,86.83 13.06,83.12 13.54,82.64 14.68,82.64 15.72,81.59 15.72,77.1 15.42,76.79 ; 4 cut-outs
V_5P0_A on TOP: 101.98,29.57 101.47,30.08 101.47,33.64 102.49,34.65 105.28,34.65 105.54,34.4 105.54,29.83 105.28,29.57
V_5P0_A on TOP: 121.18,23.2 120.52,23.86 120.52,27.72 120.97,28.17 121.78,28.17 121.79,28.18 125.07,28.18 125.5,27.75 125.5,23.71 124.99,23.2
V_5P0_A on BOTTOM: 101.09,22.46 100.71,22.84 100.71,33.26 103.76,36.31 109.09,36.31 109.73,35.67 109.73,33 110.24,32.5 122.05,32.5 123.06,31.48 123.06,30.34 123.7,29.7 123.7,25.38 123.06,24.75 120.52,24.75 120.27,25 120.27,25.89 118.11,28.05 109.35,28.05 106.17,24.88 106.17,23.99 104.65,22.46 ; 2 cut-outs
V_5P0_CONN_CRT_L on BOTTOM: 59.94,23.48 59.69,23.73 59.69,25.51 60.07,25.89 63.75,25.89 63.88,25.76 63.88,23.73 63.63,23.48 ; 1 cut-out
V_5P0_HDMI_CONN on BOTTOM: 46.99,19.29 46.74,19.54 46.74,21.32 46.99,21.57 52.2,21.57 52.58,21.95 52.58,22.84 52.7,22.97 55.37,22.97 55.5,22.84 55.5,21.32 54.48,20.3 48.51,20.3 47.5,19.29 ; 1 cut-out
V_5P0_HDMI_CONN_L on BOTTOM: 54.23,23.61 54.23,24.75 54.61,25.13 55.24,25.13 55.37,25.26 55.37,25.76 55.5,25.89 58.8,25.89 59.31,25.38 59.31,24.11 58.8,23.61
V_12_INV on TOP: 5.21,120.89 4.45,121.65 4.45,122.41 4.65,122.62 4.65,125.64 5.99,126.98 14.48,126.98 14.61,126.86 14.61,123.68 14.35,123.43 12.19,123.43 11.81,123.05 8.13,123.05 7.75,122.67 7.75,122.03 7.37,121.65 7.37,121.4 6.86,120.89 ; 1 cut-out
V_12_INV on BOTTOM: 4.85,120.76 4.32,121.29 4.32,126.37 5.28,127.34 13.92,127.34 14.12,127.14 14.12,121.8 13.08,120.76
V_12P0_A on TOP: 5.13,130.64 3.73,132.04 3.73,134.58 4.45,135.29 6.83,135.29 9.73,132.39 11.81,132.39 13.97,134.55 13.97,134.6 14.99,135.62 18.41,135.62 18.67,135.37 18.67,134.22 18.36,134.22 18.36,133.97 14.99,133.97 14.48,133.46 14.48,131.81 13.31,130.64
V_CPU_CORE on TOP: outline of 106 points within 34.67,154.16 79.8,216.65
V_CPU_CORE on BOTTOM: 72.39,158.1 71.75,158.73 71.75,159.37 72.14,159.75 72.14,160.38 72.01,160.51 71.25,160.51 70.87,160.89 70.87,163.43 69.85,164.45 50.67,164.45 42.04,173.08 40.89,173.08 35.94,178.04 35.94,180.78 34.8,181.92 34.8,190.89 35.28,191.37 38.35,191.37 39.64,192.66 39.64,193.01 39.62,193.02 39.62,195.06 41.15,196.58 41.15,208.09 40.46,208.77 34.98,208.77 34.67,209.08 34.67,213.45 35.15,213.93 38,213.93 39.7,215.63 39.7,217.38 41.76,219.44 48.51,219.44 50.55,217.41 50.55,206.99 58.42,199.12 58.42,186.17 63.33,181.26 71.59,181.26 71.94,180.91 71.94,180.27 73.77,178.43 74.41,178.43 74.42,178.42 76.33,178.42 76.58,178.67 79.25,178.67 79.76,178.16 79.76,159.75 78.11,158.1
V_SM on TOP: 143.38,147.05 142.75,147.68 142.75,163.56 145.16,165.97 179.71,165.97 180.09,165.59 180.09,162.67 179.96,162.54 174.02,162.54 173.79,162.77 173.79,163.51 172.97,164.32 170.94,164.32 170.69,164.58 167.77,164.58 167.51,164.32 163.58,164.32 162.81,163.56 162.81,148.95 162.31,148.45 159.13,148.45 158.75,148.83 158.75,163.56 157.99,164.32 153.16,164.32 152.65,164.83 151.13,164.83 150.62,164.32 148.59,164.32 147.83,163.56 147.83,147.81 147.07,147.05 ; 10 cut-outs
V_SM on TOP: 87.9,154.56 86.95,155.51 84.63,155.51 84.14,156.01 84.14,177.43 84.56,177.85 86.85,177.85 87.34,177.37 87.34,176.21 87.5,176.21 87.8,175.9 88.06,176.16 88.44,176.16 88.6,176.01 88.6,175.78 88.29,175.47 88.29,175.41 89.05,174.65 89.05,174.43 88.83,174.21 88.72,174.21 88.5,174.43 87.73,174.43 87.54,174.24 87.54,172.42 87.74,172.22 88.04,172.22 88.33,172.51 88.57,172.51 89.17,171.91 89.17,171.74 88.03,170.6 88.03,169.26 88.59,168.7 88.59,167.74 87.48,166.62 87.48,166 87.76,165.71 88.02,165.71 88.66,165.07 88.66,160.28 87.98,159.6 87.98,158.17 87.58,157.77 87.58,155.73 88.18,155.14 88.18,154.83 87.91,154.56
V_SM on TOP: 125.4,106.44 124.43,107.4 123.57,107.4 123.44,107.53 123.44,114.26 124.13,114.94 126.34,114.94 127.79,116.39 127.79,121.01 128.42,121.65 133.12,121.65 133.6,121.17 133.6,113.39 132.97,112.76 132.97,110.98 132.72,110.73 130.94,110.73 129.92,109.71 129.92,106.94 129.41,106.44 ; 2 cut-outs
V_SM on TOP: 68.33,59.8 67.56,60.56 67.56,64.37 67.94,64.75 70.99,64.75 71.25,64.5 73.28,64.5 73.53,64.25 73.53,62.72 70.61,59.8
V_SM on BOTTOM: outline of 82 points within 85.34,113.9 176.2,204.27 ; 62 cut-outs
V_SM on BOTTOM: 83.82,57.77 82.8,58.78 82.8,59.93 81.41,61.32 70.87,61.32 70.1,62.09 70.1,64.37 70.48,64.75 71.75,64.75 72.14,65.13 84.96,65.13 85.6,65.77 93.85,65.77 93.98,65.64 94.23,65.64 94.74,66.15 101.85,66.15 102.36,65.64 102.36,62.09 101.98,61.71 97.92,61.71 97.54,61.32 93.34,61.32 89.79,57.77
V_SM on L3: 99.31,68.44 99.31,70.47 107.31,78.47 109.35,78.47 111.7,80.82 111.7,100.5 121.16,109.97 128.27,109.97 129.29,108.95 129.29,104.12 128.3,103.13 125.58,103.13 118.77,96.33 118.77,89.39 116.71,87.33 116.71,79.41 101.5,64.2 97.74,64.2 97.13,64.8 97.13,66.25
V_SM_VTT on BOTTOM: 144.09,115.96 144.02,116.04 144.02,122.92 147.07,125.97 148.72,125.97 148.84,125.84 148.84,123.94 150.88,121.9 154.18,121.9 154.81,122.54 154.81,124.44 155.19,124.82 156.72,124.82 156.97,124.57 156.97,122.67 157.1,122.54 163.7,122.54 163.96,122.79 163.96,123.81 164.08,123.94 165.23,123.94 165.48,123.68 165.48,122.79 166.5,121.78 170.05,121.78 170.56,122.28 170.56,124.44 170.94,124.82 172.52,124.82 172.85,124.49 172.85,120.86 172.29,120.3 150.16,120.3 146.43,116.57 146.43,116.19 146.2,115.96 ; 7 cut-outs
VGA_CORE on TOP: 76.71,83.3 76.58,83.42 76.58,83.55 77.09,84.06 77.09,84.69 76.96,84.82 76.45,84.82 76.33,84.95 76.33,87.36 76.58,87.61 76.58,88.25 76.45,88.38 76.45,91.42 76.58,91.55 76.83,91.55 77.98,90.41 77.98,90.15 77.44,89.62 77.44,89.16 77.85,88.76 77.85,88.12 77.47,87.74 77.47,87.11 77.93,86.65 77.93,86.17 77.47,85.71 77.47,85.2 77.98,84.69 77.98,84.18 77.09,83.3
VGA_CORE on TOP: 49.28,109.58 48.9,109.97 48.9,119.49 49.02,119.36 53.72,119.36 56.39,116.7 56.39,112.38 55.37,111.36 52.93,111.36 51.16,109.58
VGA_CORE on TOP: 80.39,83.42 80.39,83.55 78.61,85.33 78.61,85.84 79.12,86.34 79.12,86.72 78.61,87.23 78.61,87.74 79.12,88.25 79.12,88.5 78.61,89.01 78.61,89.65 79.12,90.15 79.12,90.41 78.99,90.53 78.99,90.79 79.12,90.92 79.5,90.92 80.01,90.41 80.01,90.15 79.38,89.52 79.38,89.01 80.01,88.38 80.01,88.25 79.38,87.61 79.38,87.36 79.5,87.23 79.5,87.11 80.01,86.6 80.01,86.47 80.26,86.22 80.64,86.22 80.77,86.34 80.9,86.34 80.9,86.85 80.39,87.36 80.39,87.61 80.9,88.12 80.9,88.63 80.39,89.14 80.39,89.39 80.9,89.9 80.9,91.17 81.41,91.68 82.55,91.68 82.8,91.42 82.8,91.17 82.17,90.53 82.17,90.28 83.31,89.14 83.31,87.36 83.82,86.85 83.82,86.22 83.31,85.71 84.45,84.57 84.45,83.93 84.2,83.68 83.82,83.68 82.93,84.57 82.17,84.57 81.03,83.42
VGA_CORE on BOTTOM: 77.09,83.55 76.96,83.68 76.96,85.45 76.58,85.84 76.58,87.23 76.45,87.23 75.95,87.74 75.95,90.28 76.83,91.17 77.22,91.17 77.6,90.79 78.74,90.79 78.8,90.73 78.87,90.79 79.5,90.79 79.63,90.66 79.63,86.85 79.5,86.72 79.25,86.72 78.74,86.22 78.74,85.71 78.61,85.58 78.23,85.58 77.85,85.2 77.85,84.97 78.11,84.72 78.11,84.31 77.98,84.18 77.7,84.18 77.6,84.08 77.6,83.68 77.47,83.55 ; 9 cut-outs
VGA_CORE on BOTTOM: 82.42,81.87 82.22,82.08 82.22,82.61 81.92,82.91 80.26,82.91 80.01,83.17 80.01,84.44 80.64,85.07 80.64,88.5 80.9,88.76 80.9,90.92 81.15,91.17 82.3,91.17 82.68,90.79 82.68,90.41 83.19,89.9 83.19,89.14 83.41,88.91 83.41,88.5 83.34,88.43 82.75,88.43 82.68,88.5 82.68,89.01 82.55,89.14 81.79,89.14 81.66,89.01 81.66,88.5 81.84,88.33 82.22,88.33 82.3,88.25 82.3,87.49 82.42,87.36 83.31,87.36 83.95,86.72 83.95,86.34 83.57,85.96 83.57,85.33 83.82,85.07 83.82,84.62 84.35,84.08 84.35,83.85 84.25,83.75 83.41,83.75 83.16,83.5 83.17,83.49 83.17,82.01 83.03,81.87 ; 15 cut-outs
VGA_CORE on BOTTOM: 77.6,96.38 77.34,96.63 77.34,97.14 77.22,97.27 77.22,97.9 77.6,98.28 80.39,98.28 81.15,97.52 81.15,97.01 81.03,96.88 80.52,96.88 80.01,96.38 ; 4 cut-outs
VGA_CORE on BOTTOM: 49.73,110.85 49.73,119.19 49.96,119.41 51.56,119.41 51.99,118.98 54.86,118.98 56.52,117.33 56.52,112.38 55.22,111.08 52.35,111.08 52.12,110.85
VGA_CORE on L3: 73.62,124.47 59.49,124.47 55.37,120.35 52.04,120.35 51.44,119.74 51.44,112.29 51.87,111.86 64.11,111.86 65.75,110.22 67.18,110.22 75.56,101.84 75.56,101.08 75.5,101.01 75.5,100.38 75.56,100.31 75.56,97.27 76.96,95.87 76.96,83.68 77.34,83.3 88.14,83.3 91.82,86.98 91.82,93.14 94.04,95.36 94.04,106.85 89.53,111.36 86.73,111.36
VGA_CORE on L4: 51.44,113.27 51.44,119.74 52.04,120.35 55.42,120.35 59.46,124.39 69.41,124.39 85.6,108.2 85.6,108.19 91.69,102.09 91.69,90.66 89.41,88.38 89.41,88.12 84.96,83.68 80.14,83.68 76.96,86.85 76.96,89.77 76.33,90.41 76.33,94.09 76.96,94.73 76.96,97.27 74.93,99.3 74.93,99.68 71.75,102.85 69.98,102.85 60.33,112.51 52.2,112.51
VGA_CORE_PWR on TOP: 40.89,107.17 40.39,107.68 40.39,109.08 40.13,109.33 38.35,109.33 33.4,114.28 33.4,120.56 34.06,121.22 37.13,121.22 37.54,121.62 37.54,127.42 38.89,128.76 47.29,128.76 48.41,127.64 48.41,121.5 48.64,121.27 48.64,109.58 46.23,107.17
VGA_CORE_PWR on BOTTOM: 39.07,109.86 34.01,114.92 34.01,115.17 34.34,115.5 34.49,115.5 34.49,115.71 34.21,115.99 34.21,117.1 34.14,117.18 34.11,117.18 33.4,117.89 33.4,127.49 34.67,128.76 46.1,128.76 46.48,128.38 46.48,119.62 46.61,119.49 49.06,119.49 49.06,110.73 46.61,110.73 45.75,109.86

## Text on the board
Ref Des/Silkscreen Bottom: F9:2A/24V | F10:3A/32V | F14:1.5A/8V | F13:1.5A/8V | F8:2A/8V | F6:1.5A/8V | F4:1.5A/8V | F12:3A/15V | F7:1.5A/8V | F11:2A/8V
Ref Des/Silkscreen Top: F2:1.5A/8V | FAN_CPU | ATX2 | B | WWW.DELL.COM | Dell PN:70MRT | Rev:A00 | RJ1 | C | H | A | HDMI1 | VGA1 | CPU1 | D | G | F5:2A/8V | LOUT1 | X2:27MHZ | USB3 | X5:27MHZ | E | NGFF_WIFI | RTCPWR1 | USB4 | F3:1.5A/8V | USB5 | UXB6 | TC0723 | X3:25MHZ | RTCRST | PSWD | WEBCAM | MEMCD1 | SERVICE_MODE | SSUSB2 | SSUSB1 | UHS1 | X4:25MHZ | F1:3A/15V | SATA_ODD | SATA_HDD | ATX1 | PWRCN1 | SATAP1 | TOUCH | CONVERTER | INTRUDER1 | BATTERY | DIMM2 | SPEAKER | DIMM1 | LVDS | X1:32.768KHZ | Tigris AIO MB | 13048-1 | 70MRT | MADE IN TAIWAN | LAN ID
User.21: Board Accuracy Check,Dec 09 16:26:51 2013,Passed | Dummy-Static-No Shape On Layer Check,Dec 09 16:26:51 2013,Passed | Split Plane Check,Jul 23 13:46:16 2013,Passed
User.23: GND | AGND
User.24: GND | AGND
User.36: HEADER:EMN compare:1=show;2=show;3=show;4=show
User.39: ByImpedance:100.0@_REF_L1=("3.5/10.0(L1)")|_REF_L6=("3.5/10.0(L6)")|Type="DP"|_REF_L4=("4.0/9.0(L4)")|_REF_L3=("4.0/9.0(L3)")|imp="100.0" | ByImpedance:110.0@Type="DP"|_REF_L4=("3.5/13.0(L4)")|_REF_L3=("3.5/13.0(L3)")|imp="110.0" | ByImpedance:27.4@_REF_L1=("12.0(L1)")|_REF_L6=("12.0(L6)")|Type="SE"|_REF_L4=("16.0(L4)")|_REF_L3=("16.0(L3)")|imp="27.4" | ByImpedance:33.0@_REF_L1=("9.0(L1)")|_REF_L6=("9.0(L6)")|Type="SE"|_REF_L4=("12.0(L4)")|_REF_L3=("12.0(L3)")|imp="33.0" | ByImpedance:34.0@_REF_L1=("8.5(L1)")|_REF_L6=("8.5(L6)")|Type="SE"|_REF_L4=("11.5(L4)")|_REF_L3=("11.5(L3)")|imp="34.0" | ByImpedance:35.0@_REF_L1=("8.0(L1)")|_REF_L6=("8.0(L6)")|Type="SE"|_REF_L4=("10.5(L4)")|_REF_L3=("10.5(L3)")|imp="35.0" | ByImpedance:37.5@_REF_L1=("7.0(L1)")|_REF_L6=("7.0(L6)")|Type="SE"|_REF_L4=("9.5(L4)")|_REF_L3=("9.5(L3)")|imp="37.5" | ByImpedance:39.0@_REF_L1=("6.5(L1)")|_REF_L6=("6.5(L6)")|Type="SE"|_REF_L4=("9.0(L4)")|_REF_L3=("9.0(L3)")|imp="39.0" | ByImpedance:40.0@_REF_L1=("6.5(L1)")|_REF_L6=("6.5(L6)")|Type="SE"|_REF_L4=("8.5(L4)")|_REF_L3=("8.5(L3)")|imp="40.0" | ByImpedance:42.0@_REF_L1=("5.5(L1)")|_REF_L6=("5.5(L6)")|Type="SE"|_REF_L4=("7.5(L4)")|_REF_L3=("7.5(L3)")|imp="42.0" | ByImpedance:45.0@_REF_L1=("5.0(L1)")|_REF_L6=("5.0(L6)")|Type="SE"|_REF_L4=("6.5(L4)")|_REF_L3=("6.5(L3)")|imp="45.0" | ByImpedance:48.0@_REF_L1=("4.5(L1)")|_REF_L6=("4.5(L6)")|Type="SE"|_REF_L4=("5.5(L4)")|_REF_L3=("5.5(L3)")|imp="48.0" | ByImpedance:50.0@_REF_L1=("4.0(L1)")|_REF_L6=("4.0(L6)")|Type="SE"|_REF_L4=("5.0(L4)")|_REF_L3=("5.0(L3)")|imp="50.0" | ByImpedance:52.0@_REF_L1=("3.5(L1)")|_REF_L6=("3.5(L6)")|Type="SE"|_REF_L4=("4.5(L4)")|_REF_L3=("4.5(L3)")|imp="52.0" | ByImpedance:55.0@_REF_L1=("nil(L1)")|_REF_L6=("nil(L6)")|Type="SE"|_REF_L4=("4.0(L4)")|_REF_L3=("4.0(L3)")|imp="55.0" | ByImpedance:65.0@_REF_L1=("8.0/6.0(L1)")|_REF_L6=("8.0/6.0(L6)")|Type="DP"|_REF_L4=("9.0/5.0(L4)")|_REF_L3=("9.0/5.0(L3)")|imp="65.0" | ByImpedance:68.0@_REF_L1=("6.5/4.0(L1)")|_REF_L6=("6.5/4.0(L6)")|Type="DP"|_REF_L4=("7.5/4.0(L4)")|_REF_L3=("7.5/4.0(L3)")|imp="68.0" | ByImpedance:70.0@_REF_L1=("7.0/6.0(L1)")|_REF_L6=("7.0/6.0(L6)")|Type="DP"|_REF_L4=("8.0/6.0(L4)")|_REF_L3=("8.0/6.0(L3)")|imp="70.0" | ByImpedance:72.0@_REF_L1=("7.0/8.0(L1)")|_REF_L6=("7.0/8.0(L6)")|Type="DP"|_REF_L4=("7.0/5.0(L4)")|_REF_L3=("7.0/5.0(L3)")|imp="72.0" | ByImpedance:75.0@_REF_L1=("6.0/6.0(L1)")|_REF_L6=("6.0/6.0(L6)")|Type="DP"|_REF_L4=("7.0/6.0(L4)")|_REF_L3=("7.0/6.0(L3)")|imp="75.0" | ByImpedance:80.0@_REF_L1=("5.0/5.0(L1)")|_REF_L6=("5.0/5.0(L6)")|Type="DP"|_REF_L4=("6.0/6.0(L4)")|_REF_L3=("6.0/6.0(L3)")|imp="80.0" | ByImpedance:85.0@_REF_L1=("5.0/8.0(L1)" "4.0/4.5(L1)")|_REF_L6=("5.0/8.0(L6)" "4.0/4.5(L6)")|Type="DP"|_REF_L4=("5.0/5.5(L4)")|_REF_L3=("5.0/5.5(L3)")|imp="85.0" | ByImpedance:90.0@_REF_L1=("4.0/6.0(L1)")|_REF_L6=("4.0/6.0(L6)")|Type="DP"|_REF_L4=("5.0/8.0(L4)" "4.0/5.0(L4)")|_REF_L3=("5.0/8.0(L3)" "4.0/5.0(L3)")|imp="90.0" | ByImpedance:93.0@_REF_L1=("4.0/8.0(L1)" "3.5/5.5(L1)")|_REF_L6=("4.0/8.0(L6)" "3.5/5.5(L6)")|Type="DP"|_REF_L4=("5.0/9.0(L4)" "4.0/5.5(L4)")|_REF_L3=("5.0/9.0(L3)" "4.0/5.5(L3)")|imp="93.0" | ByImpedance:95.0@_REF_L1=("4.0/10.0(L1)" "3.5/6.0(L1)")|_REF_L6=("4.0/10.0(L6)" "3.5/6.0(L6)")|Type="DP"|_REF_L4=("4.0/6.5(L4)")|_REF_L3=("4.0/6.5(L3)")|imp="95.0" | LayerIndex:nil | Source:6-1.2-7a.xls | artWorks:("_REF_L3" "_REF_L4" "_REF_L6" "_REF_L1") | gtImpOutlineUsed:BOARD GEOMETRY/OUTLINE
User.40: VIA_ON_PAD_SNGL artwork for vendor reference | For VOP Process.
User.43: VIA_ON_PAD_DUAL artwork for vendor reference | For VOP Process.
